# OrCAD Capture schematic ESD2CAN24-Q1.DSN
size A
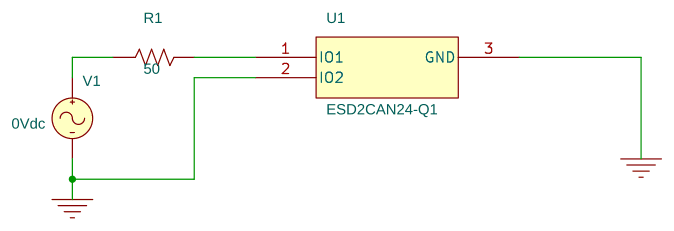
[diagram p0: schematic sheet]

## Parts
R1  50  [AXRC05]
U1  ESD2CAN24-Q1
V1  VAC

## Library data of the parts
R1 = R
U1 = ESD2CAN24-Q1
V1 = VAC: DC: 0Vdc

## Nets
0: U1.2(IO2) U1.3(GND) V1.2(-)
N00112: R1.1 V1.1(+)
N00200: R1.2 U1.1(IO1)
